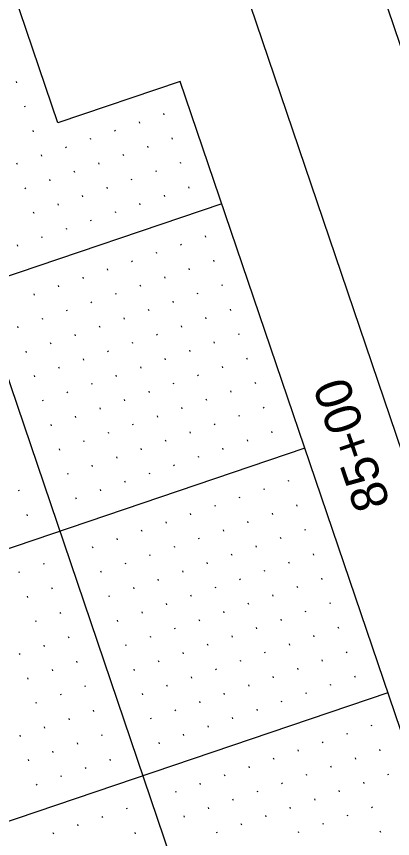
# Model space of a CAD drawing. Extents: x 2150800 to 2152547, y 141860 to 143950.
# Drawn here: x 2151908.2 to 2151980.9, y 143479.3 to 143638.5 of the extents above; entities that cross this region are included whole.
import ezdxf

# ---------------------------------------------------------------- set-up
doc = ezdxf.new("R2010")
doc.units = 0
for name, color, linetype in [('SHT_Plan_Profile_Sheet_Sta_Txt', 7, 'Continuous'), ('SHT_Plot_Shape_Half', 7, 'Continuous'), ('SHT_Profile_Grid_Major', 7, 'Continuous'), ('SHT_Profile_Grid_Minor', 7, 'Continuous'), ('SHT_Sheet_Border', 7, 'Continuous')]:
    doc.layers.add(name, color=color, linetype=linetype)

msp = doc.modelspace()

# ---------------------------------------------------------------- linework, layer by layer
at = {"layer": 'SHT_Plot_Shape_Half'}
msp.add_lwpolyline([(2151391.39, 141950.92), (2150845.24, 143560.8), (2151886.93, 143914.19), (2152433.08, 142304.31)], close=True, dxfattribs=at)
at = {"layer": 'SHT_Profile_Grid_Major'}
for p, q in [((2152314.16, 142366.92), (2151808.17, 143858.43)), ((2151947.88, 143602.23), (2151517, 143456.06)), ((2151963.95, 143554.89), (2151533.06, 143408.71)), ((2151980.01, 143507.54), (2151549.13, 143361.36))]:
    msp.add_line(p, q, dxfattribs=at)
at = {"layer": 'SHT_Profile_Grid_Minor'}
for p, q in [((2151908.27, 143625.62), (2151908.19, 143625.86)), ((2151909.87, 143620.89), (2151909.79, 143621.13)), ((2151936.76, 143619.45), (2151936.68, 143619.69)), ((2151932.03, 143617.84), (2151931.95, 143618.08)), ((2151911.48, 143616.15), (2151911.4, 143616.39)), ((2151927.29, 143616.24), (2151927.21, 143616.47)), ((2151938.37, 143614.72), (2151938.29, 143614.95)), ((2151922.56, 143614.63), (2151922.48, 143614.87)), ((2151917.82, 143613.02), (2151917.74, 143613.26)), ((2151933.63, 143613.11), (2151933.55, 143613.35)), ((2151913.09, 143611.42), (2151913.01, 143611.66)), ((2151928.9, 143611.5), (2151928.82, 143611.74)), ((2151939.97, 143609.98), (2151939.89, 143610.22)), ((2151908.35, 143609.81), (2151908.27, 143610.05)), ((2151924.16, 143609.9), (2151924.08, 143610.13)), ((2151935.24, 143608.37), (2151935.16, 143608.61)), ((2151919.43, 143608.29), (2151919.35, 143608.53)), ((2151930.5, 143606.77), (2151930.42, 143607)), ((2151914.69, 143606.68), (2151914.61, 143606.92)), ((2151925.77, 143605.16), (2151925.69, 143605.4)), ((2151941.58, 143605.25), (2151941.5, 143605.48)), ((2151909.96, 143605.08), (2151909.88, 143605.31)), ((2151936.85, 143603.64), (2151936.77, 143603.88)), ((2151921.03, 143603.55), (2151920.95, 143603.79)), ((2151932.11, 143602.03), (2151932.03, 143602.27)), ((2151916.3, 143601.95), (2151916.22, 143602.19)), ((2151927.38, 143600.43), (2151927.3, 143600.66)), ((2151911.56, 143600.34), (2151911.48, 143600.58)), ((2151922.64, 143598.82), (2151922.56, 143599.06)), ((2151917.91, 143597.21), (2151917.83, 143597.45)), ((2151944.79, 143595.78), (2151944.71, 143596.01)), ((2151913.17, 143595.61), (2151913.09, 143595.84)), ((2151940.06, 143594.17), (2151939.98, 143594.41)), ((2151908.44, 143594), (2151908.36, 143594.24)), ((2151935.32, 143592.56), (2151935.24, 143592.8)), ((2151930.59, 143590.96), (2151930.51, 143591.19)), ((2151946.4, 143591.04), (2151946.32, 143591.28)), ((2151925.85, 143589.35), (2151925.77, 143589.59)), ((2151941.66, 143589.43), (2151941.58, 143589.67)), ((2151921.12, 143587.74), (2151921.04, 143587.98)), ((2151936.93, 143587.83), (2151936.85, 143588.06)), ((2151916.38, 143586.14), (2151916.3, 143586.37)), ((2151932.2, 143586.22), (2151932.11, 143586.46)), ((2151948.01, 143586.31), (2151947.93, 143586.54)), ((2151911.65, 143584.53), (2151911.57, 143584.77)), ((2151927.46, 143584.62), (2151927.38, 143584.85)), ((2151943.27, 143584.7), (2151943.19, 143584.94)), ((2151922.73, 143583.01), (2151922.64, 143583.25)), ((2151938.54, 143583.09), (2151938.46, 143583.33)), ((2151917.99, 143581.4), (2151917.91, 143581.64)), ((2151933.8, 143581.49), (2151933.72, 143581.72)), ((2151949.61, 143581.57), (2151949.53, 143581.81)), ((2151913.26, 143579.8), (2151913.18, 143580.03)), ((2151929.07, 143579.88), (2151928.99, 143580.12)), ((2151944.88, 143579.96), (2151944.8, 143580.2)), ((2151908.52, 143578.19), (2151908.44, 143578.43)), ((2151924.33, 143578.27), (2151924.25, 143578.51)), ((2151940.14, 143578.36), (2151940.06, 143578.59)), ((2151919.6, 143576.67), (2151919.52, 143576.9)), ((2151935.41, 143576.75), (2151935.33, 143576.99)), ((2151951.22, 143576.84), (2151951.14, 143577.07)), ((2151914.86, 143575.06), (2151914.78, 143575.3)), ((2151930.67, 143575.15), (2151930.59, 143575.38)), ((2151946.48, 143575.23), (2151946.4, 143575.47)), ((2151910.13, 143573.45), (2151910.05, 143573.69)), ((2151925.94, 143573.54), (2151925.86, 143573.78)), ((2151941.75, 143573.62), (2151941.67, 143573.86)), ((2151921.2, 143571.93), (2151921.12, 143572.17)), ((2151937.01, 143572.02), (2151936.93, 143572.25)), ((2151952.83, 143572.1), (2151952.74, 143572.34)), ((2151916.47, 143570.33), (2151916.39, 143570.56)), ((2151932.28, 143570.41), (2151932.2, 143570.65)), ((2151948.09, 143570.49), (2151948.01, 143570.73)), ((2151911.73, 143568.72), (2151911.65, 143568.96)), ((2151927.54, 143568.8), (2151927.46, 143569.04)), ((2151943.36, 143568.89), (2151943.27, 143569.12)), ((2151922.81, 143567.2), (2151922.73, 143567.43)), ((2151938.62, 143567.28), (2151938.54, 143567.52)), ((2151954.43, 143567.37), (2151954.35, 143567.6)), ((2151918.07, 143565.59), (2151917.99, 143565.83)), ((2151933.89, 143565.68), (2151933.81, 143565.91)), ((2151949.7, 143565.76), (2151949.62, 143566)), ((2151913.34, 143563.99), (2151913.26, 143564.22)), ((2151929.15, 143564.07), (2151929.07, 143564.31)), ((2151944.96, 143564.15), (2151944.88, 143564.39)), ((2151924.42, 143562.46), (2151924.34, 143562.7)), ((2151940.23, 143562.55), (2151940.15, 143562.78)), ((2151956.04, 143562.63), (2151955.96, 143562.87)), ((2151919.68, 143560.86), (2151919.6, 143561.09)), ((2151935.49, 143560.94), (2151935.41, 143561.18)), ((2151951.3, 143561.02), (2151951.22, 143561.26)), ((2151914.95, 143559.25), (2151914.87, 143559.49)), ((2151930.76, 143559.33), (2151930.68, 143559.57)), ((2151946.57, 143559.42), (2151946.49, 143559.65)), ((2151926.02, 143557.73), (2151925.94, 143557.96)), ((2151941.83, 143557.81), (2151941.75, 143558.05)), ((2151957.64, 143557.9), (2151957.56, 143558.13)), ((2151921.29, 143556.12), (2151921.21, 143556.36)), ((2151937.1, 143556.21), (2151937.02, 143556.44)), ((2151952.91, 143556.29), (2151952.83, 143556.53)), ((2151916.55, 143554.52), (2151916.47, 143554.75)), ((2151932.36, 143554.6), (2151932.28, 143554.84)), ((2151948.17, 143554.68), (2151948.09, 143554.92)), ((2151927.63, 143552.99), (2151927.55, 143553.23)), ((2151943.44, 143553.08), (2151943.36, 143553.31)), ((2151922.89, 143551.39), (2151922.81, 143551.62)), ((2151938.7, 143551.47), (2151938.62, 143551.71)), ((2151918.16, 143549.78), (2151918.08, 143550.02)), ((2151933.97, 143549.86), (2151933.89, 143550.1)), ((2151929.23, 143548.26), (2151929.15, 143548.49)), ((2151960.86, 143548.43), (2151960.78, 143548.66)), ((2151908.69, 143546.57), (2151908.61, 143546.8)), ((2151924.5, 143546.65), (2151924.42, 143546.89)), ((2151956.12, 143546.82), (2151956.04, 143547.06)), ((2151919.76, 143545.05), (2151919.68, 143545.28)), ((2151951.39, 143545.21), (2151951.31, 143545.45)), ((2151946.65, 143543.61), (2151946.57, 143543.84)), ((2151962.46, 143543.69), (2151962.38, 143543.93)), ((2151910.29, 143541.83), (2151910.21, 143542.07)), ((2151941.92, 143542), (2151941.84, 143542.24)), ((2151957.73, 143542.08), (2151957.65, 143542.32)), ((2151937.18, 143540.39), (2151937.1, 143540.63)), ((2151952.99, 143540.48), (2151952.91, 143540.72)), ((2151932.45, 143538.79), (2151932.37, 143539.02)), ((2151948.26, 143538.87), (2151948.18, 143539.11)), ((2151964.07, 143538.96), (2151963.99, 143539.19)), ((2151927.71, 143537.18), (2151927.63, 143537.42)), ((2151943.52, 143537.27), (2151943.44, 143537.5)), ((2151959.33, 143537.35), (2151959.25, 143537.59)), ((2151922.98, 143535.58), (2151922.9, 143535.81)), ((2151938.79, 143535.66), (2151938.71, 143535.9)), ((2151954.6, 143535.74), (2151954.52, 143535.98)), ((2151934.05, 143534.05), (2151933.97, 143534.29)), ((2151949.86, 143534.14), (2151949.78, 143534.37)), ((2151965.68, 143534.22), (2151965.6, 143534.46)), ((2151913.51, 143532.36), (2151913.43, 143532.6)), ((2151929.32, 143532.45), (2151929.24, 143532.68)), ((2151945.13, 143532.53), (2151945.05, 143532.77)), ((2151960.94, 143532.61), (2151960.86, 143532.85)), ((2151908.77, 143530.76), (2151908.69, 143530.99)), ((2151924.58, 143530.84), (2151924.5, 143531.08)), ((2151940.39, 143530.92), (2151940.31, 143531.16)), ((2151956.21, 143531.01), (2151956.13, 143531.25)), ((2151935.66, 143529.32), (2151935.58, 143529.55)), ((2151951.47, 143529.4), (2151951.39, 143529.64)), ((2151967.28, 143529.49), (2151967.2, 143529.72)), ((2151915.11, 143527.63), (2151915.03, 143527.86)), ((2151930.92, 143527.71), (2151930.84, 143527.95)), ((2151946.74, 143527.8), (2151946.66, 143528.03)), ((2151962.55, 143527.88), (2151962.47, 143528.12)), ((2151910.38, 143526.02), (2151910.3, 143526.26)), ((2151926.19, 143526.11), (2151926.11, 143526.34)), ((2151942, 143526.19), (2151941.92, 143526.43)), ((2151957.81, 143526.27), (2151957.73, 143526.51)), ((2151937.27, 143524.58), (2151937.19, 143524.82)), ((2151953.08, 143524.67), (2151953, 143524.9)), ((2151968.89, 143524.75), (2151968.81, 143524.99)), ((2151916.72, 143522.89), (2151916.64, 143523.13)), ((2151932.53, 143522.98), (2151932.45, 143523.21)), ((2151948.34, 143523.06), (2151948.26, 143523.3)), ((2151964.15, 143523.14), (2151964.07, 143523.38)), ((2151911.98, 143521.29), (2151911.9, 143521.52)), ((2151927.8, 143521.37), (2151927.72, 143521.61)), ((2151943.61, 143521.45), (2151943.53, 143521.69)), ((2151959.42, 143521.54), (2151959.34, 143521.78)), ((2151938.87, 143519.85), (2151938.79, 143520.08)), ((2151954.68, 143519.93), (2151954.6, 143520.17)), ((2151970.49, 143520.02), (2151970.41, 143520.25)), ((2151918.33, 143518.16), (2151918.25, 143518.39)), ((2151934.14, 143518.24), (2151934.06, 143518.48)), ((2151949.95, 143518.33), (2151949.87, 143518.56)), ((2151965.76, 143518.41), (2151965.68, 143518.65)), ((2151913.59, 143516.55), (2151913.51, 143516.79)), ((2151929.4, 143516.64), (2151929.32, 143516.87)), ((2151945.21, 143516.72), (2151945.13, 143516.96)), ((2151961.02, 143516.8), (2151960.94, 143517.04)), ((2151908.86, 143514.95), (2151908.78, 143515.18)), ((2151940.48, 143515.11), (2151940.4, 143515.35)), ((2151956.29, 143515.2), (2151956.21, 143515.43)), ((2151972.1, 143515.28), (2151972.02, 143515.52)), ((2151919.93, 143513.42), (2151919.85, 143513.66)), ((2151935.74, 143513.51), (2151935.66, 143513.74)), ((2151951.55, 143513.59), (2151951.47, 143513.83)), ((2151967.37, 143513.67), (2151967.29, 143513.91)), ((2151915.2, 143511.82), (2151915.12, 143512.05)), ((2151931.01, 143511.9), (2151930.93, 143512.14)), ((2151946.82, 143511.98), (2151946.74, 143512.22)), ((2151962.63, 143512.07), (2151962.55, 143512.31)), ((2151910.46, 143510.21), (2151910.38, 143510.45)), ((2151942.09, 143510.38), (2151942, 143510.62)), ((2151957.9, 143510.46), (2151957.82, 143510.7)), ((2151973.71, 143510.55), (2151973.63, 143510.78)), ((2151921.54, 143508.69), (2151921.46, 143508.92)), ((2151937.35, 143508.77), (2151937.27, 143509.01)), ((2151953.16, 143508.86), (2151953.08, 143509.09)), ((2151968.97, 143508.94), (2151968.89, 143509.18)), ((2151916.8, 143507.08), (2151916.72, 143507.32)), ((2151932.62, 143507.17), (2151932.53, 143507.4)), ((2151948.43, 143507.25), (2151948.35, 143507.49)), ((2151964.24, 143507.33), (2151964.16, 143507.57)), ((2151912.07, 143505.48), (2151911.99, 143505.71)), ((2151943.69, 143505.64), (2151943.61, 143505.88)), ((2151959.5, 143505.73), (2151959.42, 143505.96)), ((2151923.15, 143503.95), (2151923.06, 143504.19)), ((2151938.96, 143504.04), (2151938.88, 143504.27)), ((2151954.77, 143504.12), (2151954.69, 143504.36)), ((2151918.41, 143502.35), (2151918.33, 143502.58)), ((2151934.22, 143502.43), (2151934.14, 143502.67)), ((2151950.03, 143502.51), (2151949.95, 143502.75)), ((2151913.68, 143500.74), (2151913.59, 143500.98)), ((2151945.3, 143500.91), (2151945.22, 143501.15)), ((2151976.92, 143501.08), (2151976.84, 143501.31)), ((2151908.94, 143499.13), (2151908.86, 143499.37)), ((2151924.75, 143499.22), (2151924.67, 143499.45)), ((2151940.56, 143499.3), (2151940.48, 143499.54)), ((2151972.18, 143499.47), (2151972.1, 143499.71)), ((2151920.02, 143497.61), (2151919.94, 143497.85)), ((2151935.83, 143497.7), (2151935.75, 143497.93)), ((2151967.45, 143497.86), (2151967.37, 143498.1)), ((2151915.28, 143496.01), (2151915.2, 143496.24)), ((2151962.72, 143496.26), (2151962.63, 143496.49)), ((2151978.53, 143496.34), (2151978.45, 143496.58)), ((2151910.55, 143494.4), (2151910.47, 143494.64)), ((2151926.36, 143494.48), (2151926.28, 143494.72)), ((2151957.98, 143494.65), (2151957.9, 143494.89)), ((2151973.79, 143494.74), (2151973.71, 143494.97)), ((2151921.62, 143492.88), (2151921.54, 143493.11)), ((2151953.25, 143493.04), (2151953.16, 143493.28)), ((2151969.06, 143493.13), (2151968.98, 143493.37)), ((2151916.89, 143491.27), (2151916.81, 143491.51)), ((2151948.51, 143491.44), (2151948.43, 143491.68)), ((2151964.32, 143491.52), (2151964.24, 143491.76)), ((2151980.13, 143491.61), (2151980.05, 143491.84)), ((2151912.15, 143489.66), (2151912.07, 143489.9)), ((2151943.78, 143489.83), (2151943.7, 143490.07)), ((2151959.59, 143489.92), (2151959.51, 143490.15)), ((2151975.4, 143490), (2151975.32, 143490.24)), ((2151939.04, 143488.23), (2151938.96, 143488.46)), ((2151954.85, 143488.31), (2151954.77, 143488.55)), ((2151970.66, 143488.39), (2151970.58, 143488.63)), ((2151950.12, 143486.7), (2151950.04, 143486.94)), ((2151965.93, 143486.79), (2151965.85, 143487.02)), ((2151929.57, 143485.01), (2151929.49, 143485.25)), ((2151945.38, 143485.1), (2151945.3, 143485.33)), ((2151961.19, 143485.18), (2151961.11, 143485.42)), ((2151977, 143485.27), (2151976.92, 143485.5)), ((2151924.84, 143483.41), (2151924.76, 143483.64)), ((2151940.65, 143483.49), (2151940.57, 143483.73)), ((2151956.46, 143483.57), (2151956.38, 143483.81)), ((2151972.27, 143483.66), (2151972.19, 143483.9)), ((2151920.1, 143481.8), (2151920.02, 143482.04)), ((2151951.72, 143481.97), (2151951.64, 143482.21)), ((2151967.53, 143482.05), (2151967.45, 143482.29)), ((2151915.37, 143480.19), (2151915.29, 143480.43)), ((2151931.18, 143480.28), (2151931.1, 143480.51)), ((2151946.99, 143480.36), (2151946.91, 143480.6)), ((2151962.8, 143480.45), (2151962.72, 143480.68)), ((2151978.61, 143480.53), (2151978.53, 143480.77))]:
    msp.add_line(p, q, dxfattribs=at)
at = {"layer": 'SHT_Sheet_Border'}
msp.add_line((2152361.51, 142382.99), (2151939.85, 143625.91), dxfattribs=at)
msp.add_lwpolyline([(2151383.74, 142051.28), (2150877.75, 143542.79), (2151872.09, 143880.12), (2152378.08, 142388.61)], close=True, dxfattribs=at)
msp.add_lwpolyline([(2151939.85, 143625.91), (2151916.18, 143617.88), (2151843.89, 143830.95)], dxfattribs=at)

# ---------------------------------------------------------------- texts
at = {"layer": 'SHT_Plan_Profile_Sheet_Sta_Txt'}
msp.add_text('85+00', height=7, rotation=108.7393, dxfattribs=at).set_placement((2151980.51, 143544.18))

doc.saveas('drawing.dxf')
